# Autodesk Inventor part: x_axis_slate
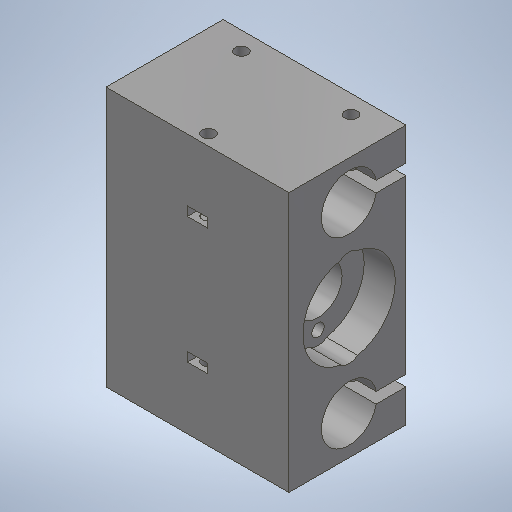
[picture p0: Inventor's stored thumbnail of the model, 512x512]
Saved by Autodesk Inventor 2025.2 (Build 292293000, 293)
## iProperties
Created: 2025-04
Part Number: x_axis_slate
Material: 1.0037 S235JR
Document SubType Name: Modeling
Designer: BennF
Density: 7.85 g/cm^3
Appearance: Stahl
Author: BennF
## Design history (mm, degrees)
sketch "Sketch2"
  geometry: L1 (-16, 35.5)-(16, 35.5); L2 (16, 35.5)-(16, -35.5); L3 (16, -35.5)-(-16, -35.5); L4 (-16, -35.5)-(-16, 35.5); 3 further points
  constraints: 8 end point, 2 midpoint, 2 parallel, 1 horizontal, 1 horizontal alignment, 1 perpendicular, 1 vertical alignment
  dimensions: "d0" = 71 distance of L3.end L1.start; "d1" = 32 distance of L1.start L1.end
extrude "Extrusion1" new body sketch "Sketch2" distance "d2" = 50; taper "d3" = 0 deg
sketch "Sketch3"
  geometry: L1 (-26.5, 7.849)-(-26.5, 16); L2 (-23.5, 7.849)-(-23.5, 16); L3 (35.5, 16)-(-35.5, 16) reference; L4 (-25, 0.45)-(-25, -7.1); L5 (-35.5, 16)-(-35.5, -16) reference; L6 (0, 16)-(0, -6.455); A1 r 7.55 centre (-25, 0.45) between (-26.5, 7.849) and (-23.5, 7.849); 1 further point
  constraints: 8 end point, 4 vertical, 3 point on circle, 2 point on line, 1 centre point, 1 midpoint, 1 other
  dimensions: "d4" = 15.1 diameter of A1; "d5" = 8 distance edge to line of A1 L3; "d6" = 3 distance between parallel lines of L2 L1; "d109" = 25 distance from line of L6 L4.start
extrude "Extrusion2" cut sketch "Sketch3" stored distance "d8" = 50; taper "d9" = 0 deg
sketch "Sketch4"
  geometry: L1 (10, 27)-(40, 27); L2 (0, 32)-(50, 32) reference; L3 (50, 32)-(50, 23.849) reference; L4 (0, 0)-(0, 32) reference; 4 further points
  constraints: 2 end point, 2 midpoint, 2 vertical alignment, 1 horizontal, 1 horizontal alignment
  dimensions: "d17" = 30 distance of L1.start L1.end; "d103" = 5 distance between parallel lines of L2 L1; "d105" = 24 distance from line of point (25, 3) L1
hole "Hole1" sketch "Sketch4" at (40, 27), (10, 27), (25, 3) diameter "d10" = 3.4; stored, may be unused: countersink angle "d14" = 90 deg, drill point angle "d16" = 0 deg; dims "d11" = 6, "d12" = 6.5, "d13" = 3.4, "d15" = 20
workplane "Work Plane1"
mirror "Mirror1"
sketch "Sketch6"
  geometry: A1 r 7.55 centre (-25, 0.45) between (-26.5, 7.849) and (-23.5, 7.849) reference; A2 r 7.55 centre (25, 0.45) between (23.5, 7.849) and (26.5, 7.849) reference; 2 further points
  constraints: 1 horizontal alignment, 1 vertical alignment
hole "Hole3" sketch "Sketch6" diameter "d36" = 3.4; stored, may be unused: countersink angle "d40" = 90 deg, drill point angle "d42" = 0 deg; dims "d37" = 8, "d38" = 4, "d39" = 2, "d41" = 8
workplane "Work Plane2"
sketch "Sketch7"
  geometry: L1 (50, 47)-(50, 0) reference; L2 (50, 10.9)-(41.5, 10.9); L3 (41.5, 10.9)-(41.5, 16.925); L4 (50, 23.5)-(0, 23.5); L5 (0, 19.25)-(50, 19.25) reference; L6 (0, 47)-(0, 0) reference; L7 (0, 10)-(4.5, 10); L8 (4.5, 10)-(4.5, 19.25); L9 (41.5, 16.925)-(35, 16.925); L10 (35, 16.925)-(35, 19.25)
  constraints: 14 end point, 4 point on line, 3 horizontal, 3 perpendicular, 1 horizontal alignment, 1 midpoint
  dimensions: "d33" = 25.2 diameter of L2 L4; "d34" = 8.5 distance of L2.start L2.end; "d73" = 4.5 distance of L7.start L7.end; "d86" = 13.15 diameter of L9 L4; "d87" = 6.5 distance of L3.end L9.end; "d90" = 27 diameter of L7 L4
revolve "Revolution1" sketch "Sketch7" stored, may be unused: angle "d35" = 90 deg
sketch "Sketch8"
  geometry: C1 r 12.6 at (0, 0) reference; A1 r 9.5 centre (0, 0) between (-9.5, 0) and (9.5, 0)
  constraints: 2 point on circle, 1 centre point, 1 coincident, 1 horizontal alignment
  dimensions: "d43" = 19 diameter of A1
hole "Hole4" sketch "Sketch8" diameter "d44" = 3.4 (= d10); stored, may be unused: countersink angle "d48" = 90 deg, drill point angle "d50" = 0 deg; dims "d45" = 5, "d46" = 6.5, "d47" = 3.4, "d49" = 20 (= d15)
workplane "Work Plane3"
workplane "Work Plane5"
sketch "Sketch11"
  geometry: L1 (-40, -0.025)-(-42.75, 1.563); L2 (-42.75, 1.563)-(-42.75, 4.738); L3 (-42.75, 4.738)-(-40, 6.326); L4 (-40, 6.326)-(-37.25, 4.738); L5 (-37.25, 4.738)-(-37.25, 1.563); L6 (-37.25, 1.563)-(-40, -0.025); L7 (-10, -0.025)-(-12.75, 1.563); L8 (-12.75, 1.563)-(-12.75, 4.738); L9 (-12.75, 4.738)-(-10, 6.326); L10 (-10, 6.326)-(-7.25, 4.738); L11 (-7.25, 4.738)-(-7.25, 1.563); L12 (-7.25, 1.563)-(-10, -0.025); L13 (-42.75, 4.738)-(-42.75, 8.151); L14 (-50, 8.151)-(0, 8.151) reference; L15 (-37.25, 4.738)-(-37.25, 8.151); L16 (-12.75, 4.738)-(-12.75, 8.151); L17 (-7.25, 4.738)-(-7.25, 8.151); L18 (-25, -17.674)-(-22.25, -19.262); L19 (-22.25, -19.262)-(-22.25, -22.437); L20 (-22.25, -22.437)-(-25, -24.025); L21 (-25, -24.025)-(-27.75, -22.437); L22 (-27.75, -22.437)-(-27.75, -19.262); L23 (-27.75, -19.262)-(-25, -17.674); L24 (-22.25, -22.437)-(-22.25, -23.849); L25 (-27.75, -22.437)-(-27.75, -23.849); L26 (-50, -23.849)-(0, -23.849) reference; C1 r 1.7 at (-40, 3.151) reference; C2 r 1.7 at (-10, 3.151) reference; C3 r 1.7 at (-25, -20.849) reference; 4 further points
  constraints: 48 end point, 6 point on line, 5 parallel, 3 coincident, 3 vertical, 2 vertical alignment, 1 collinear, 39 other
  dimensions: "d59" = 5.5 distance between parallel lines of L5 L2
extrude "Extrusion3" cut sketch "Sketch11" distance "d60" = 2.5; taper "d61" = 0 deg
workplane "Work Plane6"
sketch "Sketch12"
  geometry: L1 (40, -1.825)-(42.75, -3.412); L2 (42.75, -3.412)-(42.75, -6.588); L3 (42.75, -6.588)-(40, -8.175); L4 (40, -8.175)-(37.25, -6.588); L5 (37.25, -6.588)-(37.25, -3.412); L6 (37.25, -3.412)-(40, -1.825); L7 (42.75, -3.412)-(42.75, 0); L8 (50, 0)-(0, 0) reference; L9 (37.25, -3.412)-(37.25, 0); L10 (25, -25.825)-(27.75, -27.412); L11 (27.75, -27.412)-(27.75, -30.588); L12 (27.75, -30.588)-(25, -32.175); L13 (25, -32.175)-(22.25, -30.588); L14 (22.25, -30.588)-(22.25, -27.412); L15 (22.25, -27.412)-(25, -25.825); L16 (10, -8.175)-(7.25, -6.588); L17 (7.25, -6.588)-(7.25, -3.412); L18 (7.25, -3.412)-(10, -1.825); L19 (10, -1.825)-(12.75, -3.412); L20 (12.75, -3.412)-(12.75, -6.588); L21 (12.75, -6.588)-(10, -8.175); L22 (12.75, -3.412)-(12.75, 0); L23 (7.25, -3.412)-(7.25, 0); L24 (22.25, -30.588)-(22.25, -32); L25 (27.75, -30.588)-(27.75, -32); L26 (50, -32)-(0, -32) reference; C1 r 1.7 at (40, -5) reference; C2 r 1.7 at (25, -29) reference; C3 r 1.7 at (10, -5) reference; 4 further points
  constraints: 48 end point, 6 point on line, 4 parallel, 3 coincident, 3 vertical, 3 vertical alignment, 1 perpendicular, 39 other
  dimensions: "d63" = 5.5 distance between parallel lines of L5 L2 (= d59)
extrude "Extrusion4" cut sketch "Sketch12" distance "d64" = 2.5 (= d60); taper "d65" = 0 deg
workplane "Work Plane7"
sketch "Sketch13"
  geometry: L1 (-23.5, 15.55)-(23.5, 15.55) reference; L2 (-13.5, 15.55)-(13.5, 15.55); L3 (13.5, 15.55)-(13.5, 0); L4 (-13.5, 0)-(-13.5, 15.55); A1 r 13.5 centre (0, 0) between (13.5, 0) and (-13.5, 0) reference; A2 r 13.5 centre (0, 0) between (-13.5, 0) and (13.5, 0)
  constraints: 6 end point, 4 point on circle, 2 horizontal alignment, 1 centre point, 1 coincident, 1 horizontal, 1 parallel, 1 perpendicular, 1 point on line
extrude "Extrusion5" cut sketch "Sketch13" distance "d67" = 11; taper "d68" = 0 deg
sketch "Sketch14"
  geometry: L1 (-6.718, -6.718)-(6.718, -6.718); L2 (-6.718, 6.718)-(6.718, 6.718); L3 (-6.718, -6.718)-(0, 0); L4 (0, 0)-(-6.718, 6.718); C1 r 4.25 at (0, 0) reference; A1 r 9.5 centre (0, 0) between (-6.718, -6.718) and (6.718, -6.718); A2 r 9.5 centre (0, 0) between (-6.718, 6.718) and (-6.718, -6.718); A3 r 11.65 centre (0, 0) between (-8.238, 8.238) and (-8.238, -8.238); A4 r 7.35 centre (0, 0) between (-5.197, 5.197) and (-5.197, -5.197); A5 r 2.15 centre (-6.718, 6.718) between (-5.197, 5.197) and (-8.238, 8.238); A6 r 2.15 centre (-6.718, -6.718) between (-8.238, -8.238) and (-5.197, -5.197); A7 r 9.5 centre (0, 0) between (6.718, -6.718) and (6.718, 6.718); A8 r 11.65 centre (0, 0) between (8.238, -8.238) and (8.238, 8.238); A9 r 7.35 centre (0, 0) between (5.197, -5.197) and (5.197, 5.197); A10 r 2.15 centre (6.718, -6.718) between (5.197, -5.197) and (8.238, -8.238); A11 r 2.15 centre (6.718, 6.718) between (8.238, 8.238) and (5.197, 5.197); 1 further point
  constraints: 22 point on circle, 11 centre point, 8 end point, 8 tangent, 3 coincident, 3 concentric, 2 horizontal alignment, 2 parallel, 1 horizontal, 1 perpendicular
  dimensions: "d69" = 19 diameter of A1 (= d43); "d70" = 4.3 radial gap between concentric circles of A4 A3
extrude "Extrusion6" cut sketch "Sketch14" stored distance "d71" = 6; taper "d72" = 0 deg
sketch "Sketch19"
  geometry: C1 r 1.7 at (-9.5, 0.1) reference; C2 r 1.7 at (9.5, 0.1) reference; C3 r 3.7 at (-9.5, 0.1); C4 r 3.7 at (9.5, 0.1); 1 further point
  constraints: 2 centre point, 2 coincident, 1 equal radius
  dimensions: "d106" = 7.4 diameter of C3
extrude "Extrusion9" cut sketch "Sketch19" stored distance "d107" = 6; taper "d108" = 0 deg
body "Solid1"
hole "Hole2" sketch "Sketch6" diameter "d25" = 8.5; stored, may be unused: countersink angle "d29" = 90 deg, drill point angle "d31" = 0 deg; dims "d26" = 5, "d27" = 4, "d28" = 2, "d30" = 7.8
workplane "Work Plane4"
sketch "Sketch9"
  geometry: L1 (0, 23.849)-(0, 32) reference; C1 r 1.7 at (-40, 27) reference; C2 r 1.7 at (-10, 27) reference; C3 r 1.7 at (-25, 3) reference; 4 further points
  constraints: 3 coincident, 1 horizontal alignment
node "Projected Loop1"
other parameters: "d32" = -15.55 (= -d5 - 0.5 x d4), "d58" = -5, "d62" = -5 (= d58), "d66" = -5
